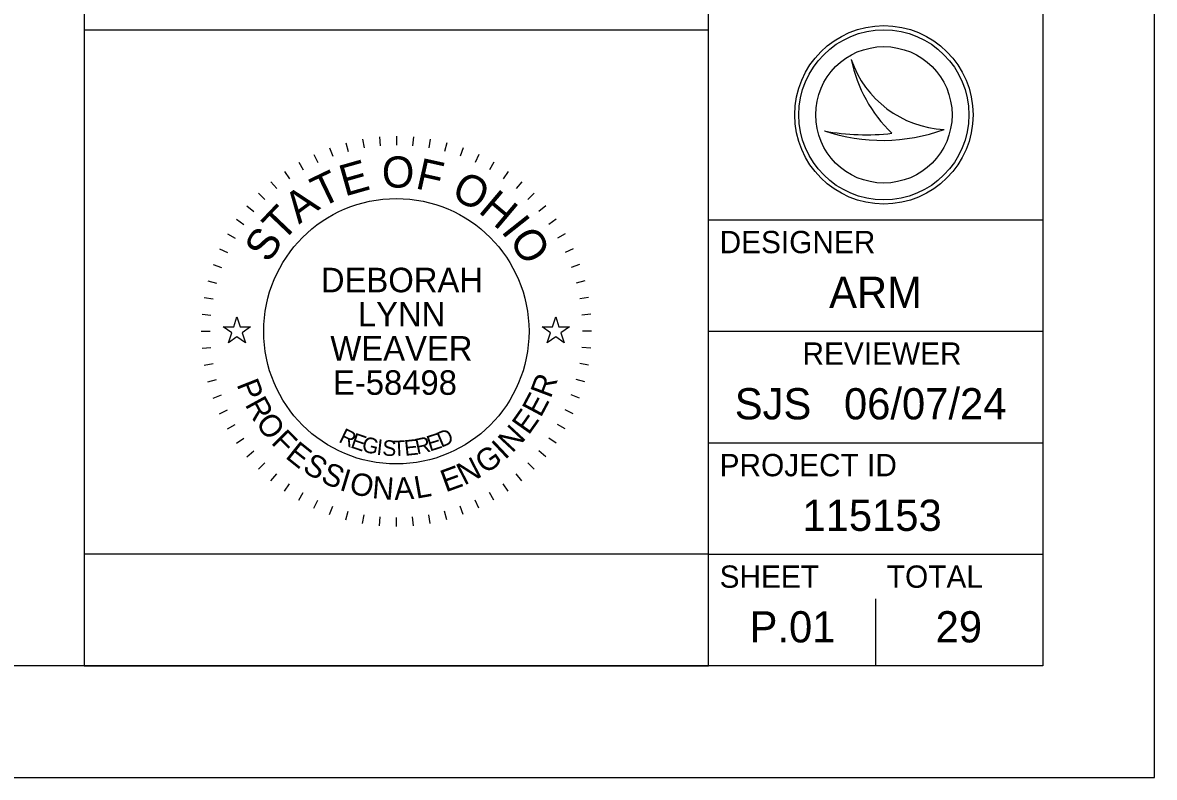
# Model space of a CAD drawing. Extents: x -7.3 to 34, y 0 to 22.
# Drawn here: x 28.92 to 34, y 0 to 3.38 of the extents above; entities that cross this region are included whole.
import ezdxf

# ---------------------------------------------------------------- set-up
doc = ezdxf.new("R2010")
doc.units = 0
for name, color, linetype in [('Default', 7, 'Continuous'), ('SH_Border', 7, 'Continuous'), ('SH_Cut_Line', 7, 'Continuous'), ('SH_Data', 7, 'Continuous')]:
    doc.layers.add(name, color=color, linetype=linetype)

msp = doc.modelspace()

# ---------------------------------------------------------------- linework, layer by layer
at = {"layer": 'Default'}
for points in [[(29.8236, 2.02), (29.8705, 2.02), (29.885, 2.0645), (29.8995, 2.02), (29.9464, 2.02), (29.9085, 1.9924), (29.923, 1.9478), (29.885, 1.9754), (29.847, 1.9478), (29.8615, 1.9924)], [(31.2536, 2.02), (31.3005, 2.02), (31.315, 2.0645), (31.3295, 2.02), (31.3764, 2.02), (31.3385, 1.9924), (31.353, 1.9478), (31.315, 1.9754), (31.277, 1.9478), (31.2915, 1.9924)]]:
    msp.add_lwpolyline(points, close=True, dxfattribs=at)
at = {"layer": 'SH_Border'}
for p, q in [((32, 0.5), (32, 21.5)), ((32, 2.5), (33.5, 2.5)), ((32, 2), (33.5, 2)), ((32, 1.5), (33.5, 1.5)), ((32, 1), (33.5, 1))]:
    msp.add_line(p, q, dxfattribs=at)
msp.add_lwpolyline([(1.5, 21.5), (33.5, 21.5), (33.5, 0.5), (1.5, 0.5)], close=True, dxfattribs=at)
at = {"layer": 'SH_Cut_Line'}
msp.add_lwpolyline([(0, 0), (34, 0), (34, 22), (0, 22)], close=True, dxfattribs=at)
at = {"layer": 'SH_Data'}
for p, q in [((29.2, 3.75), (29.2, 0.5)), ((32, 0.5), (32, 3.75)), ((32, 3.35), (29.2, 3.35)), ((32.6406, 3.218), (32.6406, 3.218)), ((32.5204, 2.898), (32.5204, 2.898)), ((33.0565, 2.9052), (33.0565, 2.9052)), ((30.3735, 2.8452), (30.3839, 2.8065)), ((30.4481, 2.8617), (30.455, 2.8223)), ((30.5237, 2.8717), (30.5272, 2.8318)), ((30.6, 2.875), (30.6, 2.835)), ((30.6763, 2.8717), (30.6728, 2.8318)), ((30.7519, 2.8617), (30.745, 2.8223)), ((30.8265, 2.8452), (30.8161, 2.8065)), ((30.2302, 2.793), (30.2471, 2.7568)), ((30.3007, 2.8222), (30.3144, 2.7846)), ((30.8993, 2.8222), (30.8856, 2.7846)), ((30.9698, 2.793), (30.9529, 2.7568)), ((30.1625, 2.7578), (30.1825, 2.7231)), ((31.0375, 2.7578), (31.0175, 2.7231)), ((30.0981, 2.7168), (30.1211, 2.684)), ((31.1019, 2.7168), (31.0789, 2.684)), ((30.0376, 2.6703), (30.0633, 2.6396)), ((31.1624, 2.6703), (31.1367, 2.6396)), ((29.9813, 2.6187), (30.0096, 2.5904)), ((31.2187, 2.6187), (31.1904, 2.5904)), ((29.9297, 2.5624), (29.9604, 2.5367)), ((31.2703, 2.5624), (31.2396, 2.5367)), ((29.8832, 2.5019), (29.916, 2.4789)), ((31.3168, 2.5019), (31.284, 2.4789)), ((29.8422, 2.4375), (29.8769, 2.4175)), ((31.3578, 2.4375), (31.3231, 2.4175)), ((29.807, 2.3698), (29.8432, 2.3529)), ((31.393, 2.3698), (31.3568, 2.3529)), ((29.7778, 2.2993), (29.8154, 2.2856)), ((31.4222, 2.2993), (31.3846, 2.2856)), ((29.7548, 2.2265), (29.7935, 2.2161)), ((31.4452, 2.2265), (31.4065, 2.2161)), ((29.7383, 2.1519), (29.7777, 2.145)), ((31.4617, 2.1519), (31.4223, 2.145)), ((29.7283, 2.0763), (29.7682, 2.0728)), ((31.4717, 2.0763), (31.4318, 2.0728)), ((29.725, 2), (29.765, 2)), ((31.475, 2), (31.435, 2)), ((29.7283, 1.9237), (29.7682, 1.9272)), ((31.4717, 1.9237), (31.4318, 1.9272)), ((29.7383, 1.8481), (29.7777, 1.855)), ((31.4617, 1.8481), (31.4223, 1.855)), ((29.7548, 1.7735), (29.7935, 1.7839)), ((31.4452, 1.7735), (31.4065, 1.7839)), ((29.7778, 1.7007), (29.8154, 1.7144)), ((31.4222, 1.7007), (31.3846, 1.7144)), ((29.807, 1.6302), (29.8432, 1.6471)), ((31.393, 1.6302), (31.3568, 1.6471)), ((29.8422, 1.5625), (29.8769, 1.5825)), ((31.3578, 1.5625), (31.3231, 1.5825)), ((29.8832, 1.4981), (29.916, 1.5211)), ((31.3168, 1.4981), (31.284, 1.5211)), ((29.9297, 1.4376), (29.9604, 1.4633)), ((31.2703, 1.4376), (31.2396, 1.4633)), ((29.9813, 1.3813), (30.0096, 1.4096)), ((31.2187, 1.3813), (31.1904, 1.4096)), ((30.0376, 1.3297), (30.0633, 1.3604)), ((31.1624, 1.3297), (31.1367, 1.3604)), ((30.0981, 1.2832), (30.1211, 1.316)), ((30.1625, 1.2422), (30.1825, 1.2769)), ((31.0375, 1.2422), (31.0175, 1.2769)), ((31.1019, 1.2832), (31.0789, 1.316)), ((30.2302, 1.207), (30.2471, 1.2432)), ((30.9698, 1.207), (30.9529, 1.2432)), ((30.3007, 1.1778), (30.3144, 1.2154)), ((30.3735, 1.1548), (30.3839, 1.1935)), ((30.4481, 1.1383), (30.455, 1.1777)), ((30.5237, 1.1283), (30.5272, 1.1682)), ((30.6763, 1.1283), (30.6728, 1.1682)), ((30.7519, 1.1383), (30.745, 1.1777)), ((30.8265, 1.1548), (30.8161, 1.1935)), ((30.8993, 1.1778), (30.8856, 1.2154)), ((30.6, 1.125), (30.6, 1.165)), ((32.75, 0.5), (32.75, 0.8)), ((32.375, 0.675), (32.375, 0.675)), ((32, 0.5), (29.2, 0.5))]:
    msp.add_line(p, q, dxfattribs=at)
msp.add_lwpolyline([(32, 0.5), (32, 1), (29.2, 1), (29.2, 0.5)], close=True, dxfattribs=at)
for centre, radius in [((32.7867, 2.9704), 0.4), ((32.7867, 2.9704), 0.3814), ((32.7867, 2.9704), 0.3814), ((32.7867, 2.9704), 0.3058), ((30.6, 2), 0.595)]:
    msp.add_circle(centre, radius, dxfattribs=at)
for centre, radius, start, end in [((33.0794, 3.3685), 0.4639, 198.9257, 198.9319), ((33.264, 3.3464), 0.6365, 191.6379, 191.6421), ((33.0794, 3.3685), 0.4639, 198.9319, 267.1657), ((33.264, 3.3464), 0.6365, 191.6421, 226.0947), ((32.7051, 3.8938), 1.0128, 259.4964, 259.4995), ((32.7782, 3.6664), 0.8105, 251.4527, 251.4576), ((32.7782, 3.6664), 0.8105, 251.4576, 290.0832), ((32.7051, 3.8938), 1.0128, 259.4995, 276.6672)]:
    msp.add_arc(centre, radius, start, end, dxfattribs=at)

# ---------------------------------------------------------------- texts
for s, height, rotation, p in [('E', 0.14, 15.7571, (30.3684, 2.6038)), ('O', 0.14, 359.7812, (30.5347, 2.6443)), ('F', 0.14, 347.4362, (30.6811, 2.6417)), ('T', 0.14, 25.7167, (30.2616, 2.5518)), ('O', 0.14, 332.2586, (30.8398, 2.6015)), ('A', 0.14, 36.4747, (30.1634, 2.4781)), ('H', 0.14, 319.9136, (30.9632, 2.5361)), ('T', 0.14, 46.4344, (30.0883, 2.3964)), ('I', 0.14, 308.367, (31.0665, 2.4483)), ('S', 0.14, 57.1924, (30.0281, 2.3014)), ('O', 0.14, 303.1491, (31.1021, 2.4089)), ('P', 0.1, 291.494, (29.8823, 1.7621)), ('R', 0.1, 69.2322, (31.2919, 1.6954)), ('E', 0.1, 61.9951, (31.2476, 1.6098)), ('R', 0.1, 298.7311, (29.919, 1.6717)), ('O', 0.1, 306.4666, (29.9655, 1.5883)), ('E', 0.1, 54.758, (31.1933, 1.5314)), ('N', 0.1, 47.0224, (31.1202, 1.4508)), ('F', 0.1, 314.7068, (30.0343, 1.4983)), ('R', 0.07, 334.487, (30.3375, 1.5051)), ('E', 0.07, 341.04, (30.3906, 1.4801)), ('G', 0.07, 347.4752, (30.4414, 1.4618)), ('R', 0.07, 11.9184, (30.6925, 1.4474)), ('E', 0.07, 17.6836, (30.7498, 1.4602)), ('D', 0.07, 23.3052, (30.801, 1.477)), ('E', 0.1, 321.4393, (30.0978, 1.4348)), ('I', 0.07, 353.7858, (30.5091, 1.4468)), ('S', 0.07, 356.8926, (30.5358, 1.4429)), ('T', 0.07, 3.0061, (30.5857, 1.4387)), ('E', 0.07, 6.0117, (30.6389, 1.4412)), ('G', 0.1, 35.0469, (30.9981, 1.357)), ('I', 0.1, 43.287, (31.0868, 1.4214)), ('S', 0.1, 328.6764, (30.1743, 1.3752)), ('N', 0.1, 27.3113, (30.9045, 1.3075)), ('S', 0.1, 335.9134, (30.2564, 1.3266)), ('I', 0.1, 343.1505, (30.3406, 1.2897)), ('E', 0.1, 20.0742, (30.8212, 1.277)), ('O', 0.1, 346.8859, (30.3839, 1.2751)), ('N', 0.1, 355.1261, (30.4888, 1.2517)), ('A', 0.1, 2.8617, (30.5923, 1.2437)), ('L', 0.1, 10.0987, (30.6894, 1.249))]:
    msp.add_text(s, height=height, rotation=rotation, dxfattribs=at).set_placement(p)
for s, height, p in [('DESIGNER', 0.1, (32.05, 2.35)), ('DEBORAH', 0.11, (30.2614, 2.1749)), ('ARM', 0.14, (32.5412, 2.105)), ('LYNN', 0.11, (30.4272, 2.0216)), ('WEAVER', 0.11, (30.304, 1.8684)), ('REVIEWER', 0.1, (32.4218, 1.85)), ('E-58498', 0.11, (30.3157, 1.7151)), ('SJS', 0.14, (32.118, 1.605)), ('06/07/24', 0.14, (32.6078, 1.605)), ('PROJECT ID', 0.1, (32.05, 1.35)), ('115153', 0.14, (32.4215, 1.105)), ('SHEET', 0.1, (32.05, 0.85)), ('TOTAL', 0.1, (32.8, 0.85)), ('P.01', 0.14, (32.1844, 0.605)), ('29', 0.14, (33.0188, 0.605))]:
    msp.add_text(s, height=height, dxfattribs=at).set_placement(p)

doc.saveas('drawing.dxf')
